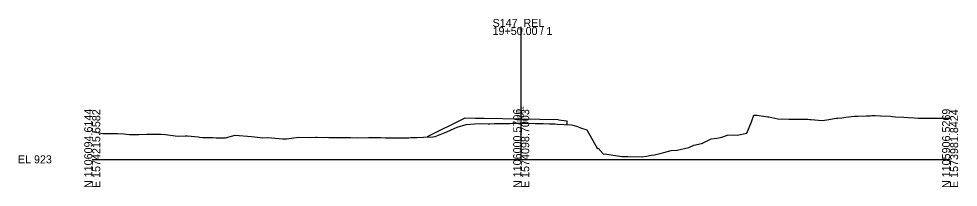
# Model space of a CAD drawing. Extents: x 1557985 to 1558314, y 1113650 to 1118205.
# Drawn here: x 1557985.4 to 1558314, y 1116650.1 to 1116708.8 of the extents above; entities that cross this region are included whole.
import ezdxf

# ---------------------------------------------------------------- set-up
doc = ezdxf.new("R2010")
doc.units = 0
for name, color, linetype in [('RD_GPK_XS_Cell', 7, 'Continuous'), ('RD_XS_EarthShd', 7, 'Continuous'), ('RD_XS_ExGround', 7, 'Continuous'), ('RD_XS_Pave', 7, 'Continuous'), ('RD_XS_TieSlope', 7, 'Continuous'), ('RD_XS_TX_Elev_EX', 7, 'Continuous'), ('RD_XS_TX_Elev_PR', 7, 'Continuous')]:
    doc.layers.add(name, color=color, linetype=linetype)

msp = doc.modelspace()

# ---------------------------------------------------------------- linework, layer by layer
at = {"layer": 'RD_GPK_XS_Cell'}
for p, q in [((1558161.13, 1116659.8), (1558161.13, 1116706)), ((1558011.13, 1116659.8), (1558161.13, 1116659.8)), ((1558161.13, 1116659.8), (1558311.13, 1116659.8))]:
    msp.add_line(p, q, dxfattribs=at)
at = {"layer": 'RD_XS_EarthShd'}
for p, q in [((1558145.13, 1116674.12), (1558141.38, 1116674.2)), ((1558148.13, 1116674.06), (1558145.13, 1116674.12)), ((1558174.13, 1116673.54), (1558177.13, 1116673.3))]:
    msp.add_line(p, q, dxfattribs=at)
at = {"layer": 'RD_XS_ExGround'}
msp.add_lwpolyline([(1558011.13, 1116669.58), (1558014.81, 1116668.84), (1558015.36, 1116668.84), (1558019.91, 1116668.86), (1558022.13, 1116668.69), (1558023.15, 1116668.61), (1558024.19, 1116668.49), (1558025.83, 1116668.43), (1558026.99, 1116668.51), (1558027.47, 1116668.53), (1558030.18, 1116668.57), (1558031.48, 1116668.63), (1558033.96, 1116668.59), (1558035.19, 1116668.54), (1558036.74, 1116668.52), (1558040.1, 1116668.02), (1558041.22, 1116667.84), (1558043.57, 1116668.03), (1558043.87, 1116668.07), (1558044.42, 1116668.03), (1558048.11, 1116667.63), (1558048.79, 1116667.6), (1558049.77, 1116667.46), (1558053.25, 1116667.38), (1558054.51, 1116667.35), (1558057.69, 1116667.34), (1558061.11, 1116668.2), (1558066.78, 1116667.75), (1558069.8, 1116667.43), (1558070.67, 1116667.35), (1558072.53, 1116667.38), (1558077.63, 1116666.93), (1558078.52, 1116666.92), (1558079.02, 1116666.97), (1558083.42, 1116667.5), (1558087.47, 1116667.49), (1558089.21, 1116667.5), (1558089.83, 1116667.51), (1558091.9, 1116667.49), (1558093.14, 1116667.53), (1558093.85, 1116667.49), (1558094.22, 1116667.44), (1558095.13, 1116667.45), (1558096.85, 1116667.43), (1558100.3, 1116667.49), (1558101.41, 1116667.48), (1558104.04, 1116667.3), (1558107.73, 1116667.39), (1558109.11, 1116667.45), (1558112.03, 1116667.39), (1558113.73, 1116667.36), (1558114.8, 1116667.31), (1558116.78, 1116667.28), (1558118.36, 1116667.26), (1558119.09, 1116667.27), (1558121.8, 1116667.35), (1558122.56, 1116667.44), (1558124.58, 1116667.49), (1558126.97, 1116667.57), (1558130.2, 1116667.72), (1558131, 1116667.81), (1558135.08, 1116669.42), (1558137.72, 1116670.63), (1558138.79, 1116671.07), (1558141.93, 1116671.96), (1558144.76, 1116672.24), (1558147.34, 1116672.28), (1558149.53, 1116672.24), (1558150.12, 1116672.24), (1558151.79, 1116672.26), (1558153.38, 1116672.28), (1558157.18, 1116672.37), (1558157.95, 1116672.42), (1558158.67, 1116672.43), (1558160.69, 1116672.43), (1558161.13, 1116672.44), (1558161.78, 1116672.46), (1558162.52, 1116672.43), (1558166, 1116672.36), (1558168.85, 1116672.27), (1558170.98, 1116672.22), (1558172.88, 1116672.19), (1558173.83, 1116672.14), (1558176.14, 1116672.02), (1558178.7, 1116671.81), (1558179.15, 1116671.78), (1558179.66, 1116671.67), (1558180.51, 1116671.42), (1558180.83, 1116671.29), (1558181.92, 1116670.85), (1558184.08, 1116670.11), (1558187.79, 1116663.51), (1558188.02, 1116663.67), (1558189.79, 1116661.72), (1558191.03, 1116661.62), (1558196.29, 1116660.86), (1558198.37, 1116660.82), (1558203.48, 1116660.72), (1558204.94, 1116660.96), (1558206.62, 1116661.28), (1558207.73, 1116661.44), (1558211.02, 1116662.18), (1558213.63, 1116662.86), (1558215.72, 1116663), (1558219.71, 1116663.97), (1558221.53, 1116664.79), (1558224.2, 1116665.36), (1558224.57, 1116665.42), (1558227.56, 1116666.92), (1558229.52, 1116667.23), (1558231.25, 1116667.6), (1558233.28, 1116668.23), (1558235.29, 1116668.41), (1558236.7, 1116668.24), (1558240.07, 1116668.96), (1558241.62, 1116672.94), (1558242.49, 1116675.19), (1558243.5, 1116675.2), (1558247.36, 1116674.64), (1558247.76, 1116674.6), (1558250.85, 1116673.94), (1558254.69, 1116673.84), (1558256.46, 1116673.84), (1558257.87, 1116673.78), (1558261.38, 1116673.78), (1558262.07, 1116673.74), (1558262.55, 1116673.73), (1558266.43, 1116673.34), (1558268.04, 1116673.54), (1558271.24, 1116674.15), (1558271.86, 1116674.17), (1558273.22, 1116674.3), (1558274.7, 1116674.55), (1558277.65, 1116674.85), (1558278.08, 1116674.88), (1558278.83, 1116674.9), (1558281.85, 1116674.99), (1558283.22, 1116675.04), (1558283.73, 1116675.06), (1558284.91, 1116675.07), (1558286.8, 1116675.04), (1558290.28, 1116674.82), (1558291.04, 1116674.78), (1558292.06, 1116674.66), (1558294.96, 1116674.47), (1558296.45, 1116674.4), (1558298.69, 1116674.24), (1558299.94, 1116674.16), (1558301.13, 1116674.14), (1558303.74, 1116674.15), (1558304.49, 1116674.14), (1558306.41, 1116674.18), (1558307.76, 1116674.2), (1558308.67, 1116674.22), (1558309.84, 1116674.19), (1558310.69, 1116674.15), (1558311.13, 1116674.14)], dxfattribs=at)
at = {"layer": 'RD_XS_Pave'}
for p, q in [((1558161.13, 1116673.8), (1558148.13, 1116674.06)), ((1558174.13, 1116673.54), (1558161.13, 1116673.8))]:
    msp.add_line(p, q, dxfattribs=at)
at = {"layer": 'RD_XS_TieSlope'}
for p, q in [((1558141.38, 1116674.2), (1558128.24, 1116667.63)), ((1558177.13, 1116673.3), (1558177.13, 1116671.94))]:
    msp.add_line(p, q, dxfattribs=at)

# ---------------------------------------------------------------- texts
at = {"layer": 'RD_GPK_XS_Cell'}
for s, p in [('S147_REL', (1558151.13, 1116706)), ('19+50.00 / 1', (1558151.13, 1116703.2)), ('EL 923', (1557985.13, 1116658.4))]:
    msp.add_text(s, height=2.8, dxfattribs=at).set_placement(p)
for s, p in [('N 1106094.6144', (1558011.13, 1116649.8)), ('E 1574215.5582', (1558013.93, 1116649.8)), ('N 1106000.5706', (1558161.13, 1116649.8)), ('E 1574098.7003', (1558163.93, 1116649.8)), ('N 1105906.5269', (1558311.13, 1116649.8)), ('E 1573981.8424', (1558313.93, 1116649.8))]:
    msp.add_text(s, height=2.8, rotation=90, dxfattribs=at).set_placement(p)
at = {"layer": 'RD_XS_TX_Elev_EX'}
msp.add_text('935.65', height=1, rotation=90, dxfattribs=at).set_placement((1558160.63, 1116672.94))
at = {"layer": 'RD_XS_TX_Elev_PR'}
msp.add_text(' 937.01', height=1, rotation=90, dxfattribs=at).set_placement((1558162.13, 1116673.8))

doc.saveas('drawing.dxf')
